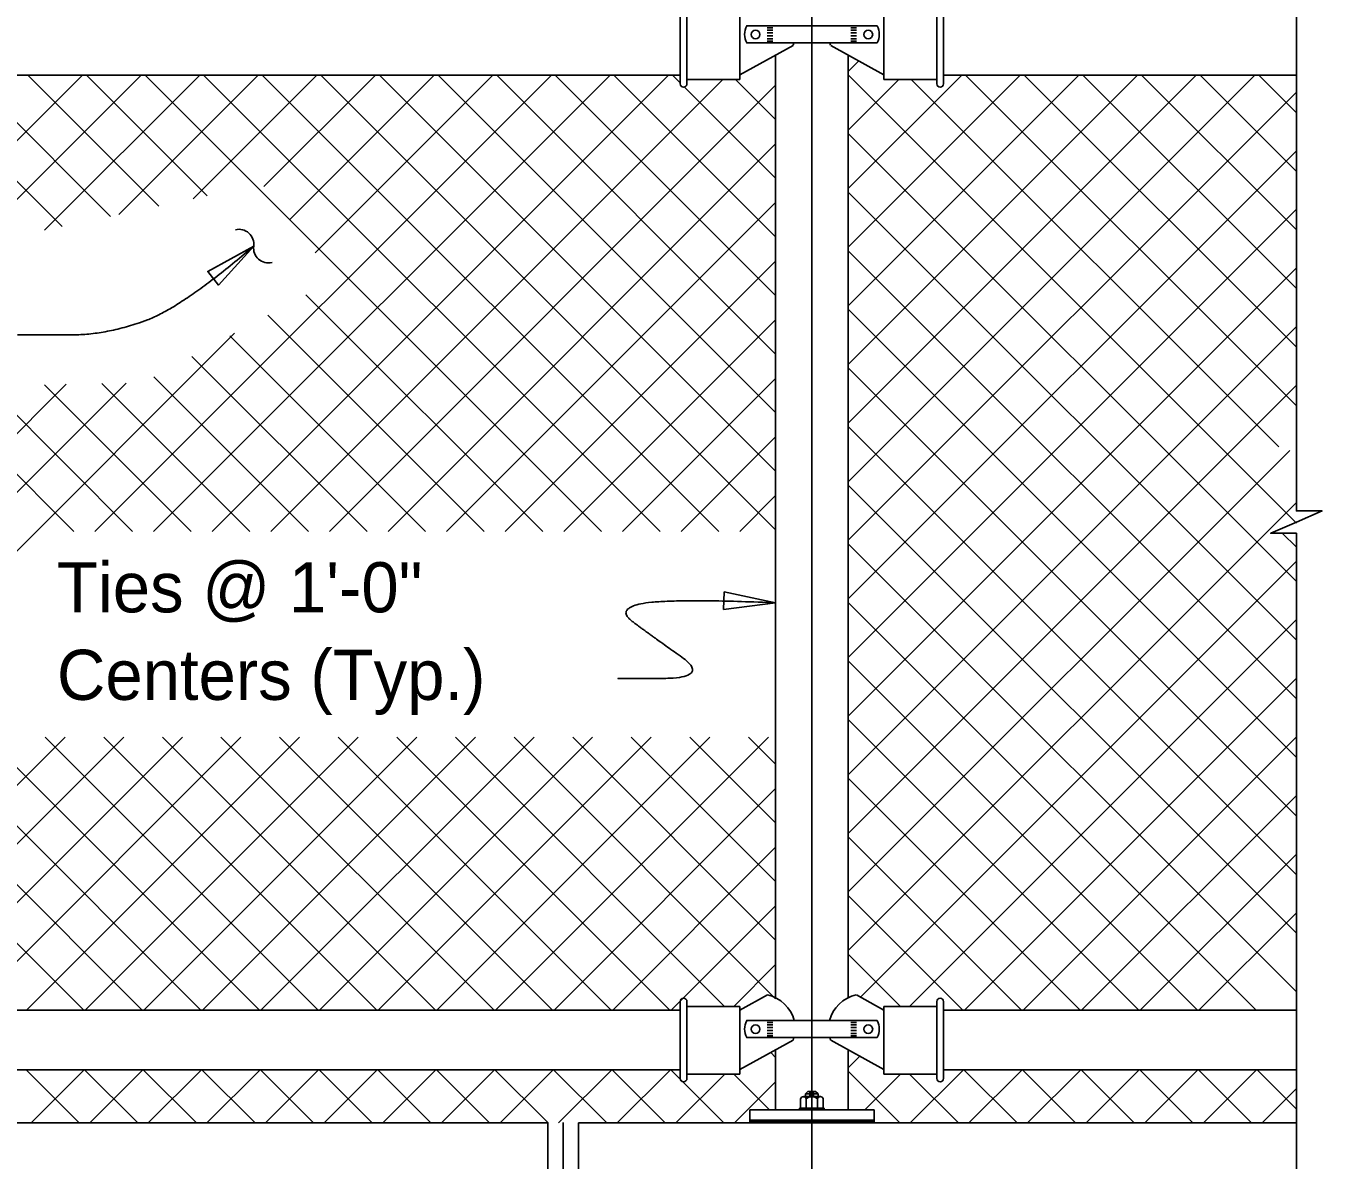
# Model space of a CAD drawing. Extents: x 110341.7 to 110413.5, y 110387.3 to 110417.8.
# Drawn here: x 110362.42 to 110367.63, y 110405.94 to 110410.5 of the extents above; entities that cross this region are included whole.
import ezdxf

# ---------------------------------------------------------------- set-up
doc = ezdxf.new("R2010")
doc.units = 0
for name, color, linetype in [('AdhocPoint_dp', 7, 'Continuous'), ('Border', 7, 'Continuous'), ('CL_Major', 7, 'Continuous'), ('Patterning', 7, 'Continuous'), ('PlotBorder_dp', 7, 'Continuous')]:
    doc.layers.add(name, color=color, linetype=linetype)

msp = doc.modelspace()

# ---------------------------------------------------------------- linework, layer by layer
at = {"layer": 'AdhocPoint_dp'}
for p, q in [((110365.0484, 110410.5816), (110365.0484, 110410.272)), ((110365.0753, 110410.5816), (110365.0753, 110410.272)), ((110365.2882, 110410.5621), (110365.2882, 110410.2898)), ((110365.8673, 110410.5621), (110365.8673, 110410.2898)), ((110366.0803, 110410.5816), (110366.0803, 110410.272)), ((110366.1071, 110410.5816), (110366.1071, 110410.272)), ((110365.8402, 110410.5047), (110365.3154, 110410.5047)), ((110365.3978, 110410.4969), (110365.4212, 110410.4969)), ((110365.3978, 110410.4873), (110365.4212, 110410.4873)), ((110365.3978, 110410.4765), (110365.4212, 110410.4765)), ((110365.3978, 110410.4647), (110365.4212, 110410.4647)), ((110365.7578, 110410.4969), (110365.7343, 110410.4969)), ((110365.7578, 110410.4873), (110365.7343, 110410.4873)), ((110365.7578, 110410.4765), (110365.7343, 110410.4765)), ((110365.7578, 110410.4647), (110365.7343, 110410.4647)), ((110365.2882, 110410.308), (110365.5022, 110410.4265)), ((110365.8402, 110410.4369), (110365.3154, 110410.4369)), ((110365.3978, 110410.453), (110365.4212, 110410.453)), ((110365.3978, 110410.4432), (110365.4212, 110410.4432)), ((110365.8673, 110410.308), (110365.6534, 110410.4265)), ((110365.7578, 110410.453), (110365.7343, 110410.453)), ((110365.7578, 110410.4432), (110365.7343, 110410.4432)), ((110365.432, 110406.5968), (110365.432, 110410.3876)), ((110365.7237, 110406.5968), (110365.7237, 110410.3876)), ((110365.0484, 110410.307), (110361.1164, 110410.307)), ((110367.5259, 110410.307), (110366.1071, 110410.307)), ((110365.0753, 110410.2898), (110365.2882, 110410.2898)), ((110366.0803, 110410.2898), (110365.8673, 110410.2898)), ((110365.2882, 110406.5473), (110365.3991, 110406.6087)), ((110365.8673, 110406.5473), (110365.7565, 110406.6087)), ((110365.0484, 110406.5466), (110361.1164, 110406.5466)), ((110365.0484, 110406.5816), (110365.0484, 110406.2719)), ((110365.0753, 110406.5816), (110365.0753, 110406.2719)), ((110365.2882, 110406.5621), (110365.0753, 110406.5621)), ((110365.2882, 110406.5621), (110365.2882, 110406.2898)), ((110365.8673, 110406.5621), (110365.8673, 110406.2898)), ((110365.8673, 110406.5621), (110366.0803, 110406.5621)), ((110366.0803, 110406.5816), (110366.0803, 110406.2719)), ((110366.1071, 110406.5816), (110366.1071, 110406.2719)), ((110367.5259, 110406.5466), (110366.1071, 110406.5466)), ((110365.8402, 110406.5047), (110365.3154, 110406.5047)), ((110365.3978, 110406.4969), (110365.4212, 110406.4969)), ((110365.7578, 110406.4969), (110365.7343, 110406.4969)), ((110365.3978, 110406.4873), (110365.4212, 110406.4873)), ((110365.3978, 110406.4765), (110365.4212, 110406.4765)), ((110365.3978, 110406.4647), (110365.4212, 110406.4647)), ((110365.3978, 110406.4529), (110365.4212, 110406.4529)), ((110365.3978, 110406.4431), (110365.4212, 110406.4431)), ((110365.7578, 110406.4873), (110365.7343, 110406.4873)), ((110365.7578, 110406.4765), (110365.7343, 110406.4765)), ((110365.7578, 110406.4647), (110365.7343, 110406.4647)), ((110365.7578, 110406.4529), (110365.7343, 110406.4529)), ((110365.7578, 110406.4431), (110365.7343, 110406.4431)), ((110365.2882, 110406.3079), (110365.5022, 110406.4265)), ((110365.8402, 110406.4369), (110365.3154, 110406.4369)), ((110365.8673, 110406.3079), (110365.6534, 110406.4265)), ((110365.432, 110406.1455), (110365.432, 110406.3876)), ((110365.7237, 110406.1455), (110365.7237, 110406.3875)), ((110365.0484, 110406.307), (110361.1164, 110406.307)), ((110365.0753, 110406.2898), (110365.2882, 110406.2898)), ((110366.0803, 110406.2898), (110365.8673, 110406.2898)), ((110367.5259, 110406.307), (110366.1071, 110406.307)), ((110365.5324, 110406.1903), (110365.5324, 110406.1526)), ((110365.6119, 110406.199), (110365.5437, 110406.199)), ((110365.5617, 110406.2199), (110365.552, 110406.2102)), ((110365.552, 110406.2102), (110365.552, 110406.199)), ((110365.552, 110406.2102), (110365.6035, 110406.2102)), ((110365.5551, 110406.1905), (110365.5551, 110406.1526)), ((110365.5617, 110406.2199), (110365.5922, 110406.2199)), ((110365.5922, 110406.2199), (110365.6035, 110406.2102)), ((110365.6005, 110406.1905), (110365.6005, 110406.1526)), ((110365.6035, 110406.2102), (110365.6035, 110406.199)), ((110365.6232, 110406.1903), (110365.6232, 110406.1526)), ((110365.5281, 110406.1526), (110365.5281, 110406.1455)), ((110365.5281, 110406.1526), (110365.6276, 110406.1526)), ((110365.6232, 110406.1526), (110365.5324, 110406.1526)), ((110365.6276, 110406.1526), (110365.6276, 110406.1455)), ((110365.458, 110406.1039), (110365.6976, 110406.1039))]:
    msp.add_line(p, q, dxfattribs=at)
msp.add_lwpolyline([(110365.3278, 110406.1455), (110365.8278, 110406.1455), (110365.8278, 110406.1039), (110365.3278, 110406.1039)], close=True, dxfattribs=at)
for centre, radius, start, end in [((110365.062, 110410.2717), 0.0134, 180, 0), ((110366.0936, 110410.2717), 0.0134, 180, 0), ((110365.062, 110406.5815), 0.0134, 0, 180), ((110366.0936, 110406.5815), 0.0134, 0, 180), ((110365.062, 110406.2717), 0.0134, 180, 0), ((110366.0936, 110406.2717), 0.0134, 180, 0), ((110365.5438, 110406.1871), 0.0118, 16.5986, 164.7005), ((110365.5778, 110406.1642), 0.0347, 49.2015, 130.7985), ((110365.6118, 110406.1872), 0.0118, 15.1506, 163.5042)]:
    msp.add_arc(centre, radius, start, end, dxfattribs=at)
for centre, major_axis, start_param, end_param in [((110365.3846, 110410.4707), (-0.0776, 0), 5.810211, 6.75616), ((110365.771, 110410.4707), (0.0776, 0), 5.810211, 6.75616), ((110365.3646, 110410.4727), (0.146, 0), 5.947976, 6.024627), ((110365.791, 110410.4727), (-0.146, 0), 0.258558, 0.335209), ((110365.3646, 110406.4727), (0.146, 0), 0.231126, 1.331255), ((110365.791, 110406.4727), (-0.146, 0), 4.95193, 6.05206), ((110365.3846, 110406.4707), (-0.0776, 0), 5.810211, 6.75616), ((110365.771, 110406.4707), (0.0776, 0), 5.810211, 6.75616), ((110365.3646, 110406.4727), (0.146, 0), 5.947976, 6.024627), ((110365.791, 110406.4727), (-0.146, 0), 0.258558, 0.335209)]:
    msp.add_ellipse(centre, major_axis=major_axis, ratio=0.957868, start_param=start_param, end_param=end_param, dxfattribs=at)
for centre, major_axis in [((110365.3512, 110410.4703), (0.0178, 0)), ((110365.8044, 110410.4703), (-0.0178, 0)), ((110365.3512, 110406.4703), (0.0178, 0)), ((110365.8044, 110406.4703), (-0.0178, 0))]:
    msp.add_ellipse(centre, major_axis=major_axis, ratio=0.957868, dxfattribs=at)
at = {"layer": 'Border'}
msp.add_line((110365.5778, 110406.1533), (110365.5778, 110406.1526), dxfattribs=at)
for points in [[(110367.5259, 110413.4227), (110367.5259, 110410.8892), (110367.6293, 110410.8892), (110367.5259, 110410.8442), (110367.4226, 110410.7992), (110367.5259, 110410.7992), (110367.5259, 110410.307)], [(110367.5259, 110410.307), (110367.5259, 110408.5545), (110367.6293, 110408.5545), (110367.5259, 110408.5095), (110367.4226, 110408.4645), (110367.5259, 110408.4645), (110367.5259, 110406.2602)], [(110367.5259, 110406.5102), (110367.5259, 110404.6594), (110367.6293, 110404.6594), (110367.5259, 110404.6144), (110367.4226, 110404.5694), (110367.5259, 110404.5694), (110367.5259, 110403.0269)]]:
    msp.add_lwpolyline(points, dxfattribs=at)
for points in [[(110363.3338, 110409.6187), (110363.1483, 110409.5178), (110363.1919, 110409.4623)], [(110365.432, 110408.1851), (110365.2253, 110408.2289), (110365.2225, 110408.1584)]]:
    msp.add_lwpolyline(points, close=True, dxfattribs=at)
for centre, start, end in [((110363.2743, 110409.6272), 352.3426, 104.0698), ((110363.3924, 110409.6113), 172.3426, 284.0698)]:
    msp.add_arc(centre, 0.0596, start, end, dxfattribs=at)
for points in [[(110362.3836, 110409.2623), (110362.4628, 110409.2623), (110362.7363, 110409.2623), (110363.0431, 110409.3702), (110363.3333, 110409.6192)], [(110364.8073, 110407.8805), (110364.7561, 110407.8805), (110365.1761, 110407.8805), (110364.9259, 110408.0576), (110364.7887, 110408.1603), (110364.9992, 110408.2028), (110365.432, 110408.1851)]]:
    msp.add_open_spline(points, degree=2, dxfattribs=at)
at = {"layer": 'CL_Major'}
for p, q in [((110365.5778, 110401.2111), (110365.5778, 110414.9771)), ((110364.5779, 110401.2111), (110364.5779, 110406.0949))]:
    msp.add_line(p, q, dxfattribs=at)
at = {"layer": 'Patterning'}
for p, q in [((110365.7237, 110410.3219), (110365.766, 110410.3642)), ((110361.9358, 110409.5981), (110362.6447, 110410.307)), ((110361.9534, 110410.307), (110362.5625, 110409.6979)), ((110362.1891, 110410.307), (110362.7571, 110409.739)), ((110362.1929, 110409.6196), (110362.8804, 110410.307)), ((110362.4248, 110410.307), (110362.9516, 110409.7802)), ((110362.492, 110409.6829), (110363.1161, 110410.307)), ((110362.6605, 110410.307), (110363.1461, 110409.8214)), ((110362.6948, 110408.4715), (110364.5303, 110410.307)), ((110362.791, 110409.7462), (110363.3518, 110410.307)), ((110362.8962, 110410.307), (110364.7317, 110408.4715)), ((110362.9305, 110408.4715), (110364.766, 110410.307)), ((110363.09, 110409.8095), (110363.5875, 110410.307)), ((110363.1319, 110410.307), (110364.9674, 110408.4715)), ((110363.1662, 110408.4715), (110365.0017, 110410.307)), ((110363.3676, 110410.307), (110365.2031, 110408.4715)), ((110363.3746, 110409.8584), (110363.8232, 110410.307)), ((110363.4774, 110409.7255), (110364.0589, 110410.307)), ((110363.5802, 110409.5926), (110364.2946, 110410.307)), ((110363.6033, 110410.307), (110365.432, 110408.4783)), ((110363.839, 110410.307), (110365.432, 110408.714)), ((110364.0747, 110410.307), (110365.432, 110408.9497)), ((110364.3104, 110410.307), (110365.432, 110409.1854)), ((110364.5461, 110410.307), (110365.432, 110409.4211)), ((110364.7818, 110410.307), (110365.432, 110409.6568)), ((110365.0175, 110410.307), (110365.0484, 110410.2761)), ((110365.7237, 110410.308), (110367.526, 110408.5057)), ((110365.7237, 110408.672), (110367.3587, 110410.307)), ((110365.7237, 110408.9077), (110367.123, 110410.307)), ((110365.7237, 110409.1434), (110366.8873, 110410.307)), ((110365.7237, 110409.6148), (110366.4159, 110410.307)), ((110365.7237, 110409.8505), (110366.1802, 110410.307)), ((110365.7237, 110409.3791), (110366.6516, 110410.307)), ((110366.196, 110410.307), (110367.526, 110408.9771)), ((110366.4317, 110410.307), (110367.526, 110409.2128)), ((110366.6674, 110410.307), (110367.526, 110409.4485)), ((110366.9031, 110410.307), (110367.526, 110409.6842)), ((110367.1388, 110410.307), (110367.526, 110409.9199)), ((110367.3745, 110410.307), (110367.526, 110410.1556)), ((110363.4019, 110408.4715), (110365.2203, 110410.2899)), ((110363.6376, 110408.4715), (110365.432, 110410.2659)), ((110365.0657, 110410.2588), (110365.432, 110409.8925)), ((110365.2704, 110410.2899), (110365.432, 110410.1282)), ((110365.7237, 110410.0862), (110365.9274, 110410.2899)), ((110365.9775, 110410.2899), (110367.4552, 110408.8121)), ((110365.7237, 110408.4363), (110367.526, 110410.2386)), ((110365.7237, 110410.0723), (110367.526, 110408.27)), ((110363.8733, 110408.4715), (110365.432, 110410.0302)), ((110365.7237, 110408.2006), (110367.526, 110410.0029)), ((110365.7237, 110409.8366), (110367.526, 110408.0343)), ((110364.109, 110408.4715), (110365.432, 110409.7945)), ((110365.7237, 110407.9649), (110367.526, 110409.7672)), ((110365.7237, 110409.6009), (110367.526, 110407.7986)), ((110364.3447, 110408.4715), (110365.432, 110409.5588)), ((110365.7237, 110407.7292), (110367.526, 110409.5315)), ((110363.5435, 110409.424), (110364.496, 110408.4715)), ((110365.7237, 110409.3652), (110367.526, 110407.5629)), ((110363.3905, 110409.3413), (110364.2603, 110408.4715)), ((110364.5804, 110408.4715), (110365.432, 110409.3231)), ((110360.5342, 110406.5466), (110363.2565, 110409.269)), ((110363.2375, 110409.2587), (110364.0246, 110408.4715)), ((110365.7237, 110407.4935), (110367.526, 110409.2958)), ((110363.0844, 110409.176), (110363.7889, 110408.4715)), ((110365.7237, 110409.1295), (110367.526, 110407.3272)), ((110360.0628, 110406.5466), (110362.5797, 110409.0635)), ((110360.2985, 110406.5466), (110362.8207, 110409.0688)), ((110362.0303, 110409.0515), (110362.6104, 110408.4715)), ((110362.261, 110409.0566), (110362.8461, 110408.4715)), ((110362.4917, 110409.0616), (110363.0818, 110408.4715)), ((110362.7223, 110409.0667), (110363.3175, 110408.4715)), ((110362.9314, 110409.0933), (110363.5532, 110408.4715)), ((110364.8161, 110408.4715), (110365.432, 110409.0874)), ((110365.7237, 110407.2578), (110367.526, 110409.0601)), ((110360.185, 110409.0112), (110362.6497, 110406.5466)), ((110360.4157, 110409.0163), (110362.8854, 110406.5466)), ((110360.6464, 110409.0213), (110363.1211, 110406.5466)), ((110360.877, 110409.0264), (110363.3568, 110406.5466)), ((110365.7237, 110408.8938), (110367.5259, 110407.0915)), ((110365.0518, 110408.4715), (110365.432, 110408.8517)), ((110365.7237, 110407.0221), (110367.4995, 110408.7979)), ((110365.7237, 110408.6581), (110367.5259, 110406.8558)), ((110365.2875, 110408.4715), (110365.432, 110408.616)), ((110365.7237, 110406.7864), (110367.526, 110408.5887)), ((110365.7237, 110408.4224), (110367.5259, 110406.6201)), ((110367.4694, 110408.4646), (110367.526, 110408.408)), ((110365.7727, 110406.5997), (110367.526, 110408.353)), ((110365.7237, 110408.1867), (110367.3637, 110406.5466)), ((110365.9708, 110406.5621), (110367.526, 110408.1172)), ((110365.7237, 110407.9509), (110367.128, 110406.5466)), ((110366.191, 110406.5466), (110367.526, 110407.8815)), ((110365.7237, 110407.7152), (110366.8923, 110406.5466)), ((110361.477, 110406.5466), (110362.5749, 110407.6446)), ((110361.7127, 110406.5466), (110362.8106, 110407.6446)), ((110361.9484, 110406.5466), (110363.0463, 110407.6446)), ((110362.1841, 110406.5466), (110363.282, 110407.6446)), ((110362.4198, 110406.5466), (110363.5177, 110407.6446)), ((110362.4945, 110407.6446), (110363.5925, 110406.5466)), ((110362.6555, 110406.5466), (110363.7534, 110407.6446)), ((110362.7302, 110407.6446), (110363.8282, 110406.5466)), ((110362.8912, 110406.5466), (110363.9891, 110407.6446)), ((110362.9659, 110407.6446), (110364.0639, 110406.5466)), ((110363.1269, 110406.5466), (110364.2248, 110407.6446)), ((110363.2016, 110407.6446), (110364.2996, 110406.5466)), ((110363.3626, 110406.5466), (110364.4605, 110407.6446)), ((110363.4373, 110407.6446), (110364.5353, 110406.5466)), ((110363.5983, 110406.5466), (110364.6962, 110407.6446)), ((110363.673, 110407.6446), (110364.771, 110406.5466)), ((110363.834, 110406.5466), (110364.932, 110407.6446)), ((110363.9087, 110407.6446), (110365.0067, 110406.5466)), ((110364.0697, 110406.5466), (110365.1677, 110407.6446)), ((110364.1444, 110407.6446), (110365.2269, 110406.5621)), ((110364.3054, 110406.5466), (110365.4034, 110407.6446)), ((110364.3801, 110407.6446), (110365.432, 110406.5927)), ((110364.6159, 110407.6446), (110365.432, 110406.8284)), ((110364.8516, 110407.6446), (110365.432, 110407.0641)), ((110365.0873, 110407.6446), (110365.432, 110407.2998)), ((110365.323, 110407.6446), (110365.432, 110407.5355)), ((110366.4267, 110406.5466), (110367.526, 110407.6458)), ((110364.5411, 110406.5466), (110365.432, 110407.4375)), ((110365.7237, 110407.4795), (110366.6566, 110406.5466)), ((110366.6624, 110406.5466), (110367.526, 110407.4101)), ((110365.7237, 110407.2438), (110366.4209, 110406.5466)), ((110364.7768, 110406.5466), (110365.432, 110407.2018)), ((110366.8981, 110406.5466), (110367.5259, 110407.1744)), ((110365.0125, 110406.5466), (110365.432, 110406.9661)), ((110365.7237, 110407.0081), (110366.1852, 110406.5466)), ((110367.1338, 110406.5466), (110367.5259, 110406.9387)), ((110365.7237, 110406.7724), (110365.9341, 110406.5621)), ((110365.2637, 110406.5621), (110365.432, 110406.7304)), ((110365.4123, 110406.3767), (110365.432, 110406.357)), ((110365.7237, 110406.3149), (110365.7704, 110406.3617)), ((110362.4178, 110406.307), (110362.6314, 110406.0935)), ((110362.4381, 110406.0935), (110362.6516, 110406.307)), ((110362.6535, 110406.307), (110362.8671, 110406.0935)), ((110362.6738, 110406.0935), (110362.8873, 110406.307)), ((110362.8892, 110406.307), (110363.1028, 110406.0935)), ((110362.9095, 110406.0935), (110363.123, 110406.307)), ((110363.125, 110406.307), (110363.3385, 110406.0935)), ((110363.1452, 110406.0935), (110363.3587, 110406.307)), ((110363.3607, 110406.307), (110363.5742, 110406.0935)), ((110363.3809, 110406.0935), (110363.5944, 110406.307)), ((110363.5964, 110406.307), (110363.8099, 110406.0935)), ((110363.6166, 110406.0935), (110363.8301, 110406.307)), ((110363.8321, 110406.307), (110364.0456, 110406.0935)), ((110363.8523, 110406.0935), (110364.0658, 110406.307)), ((110364.0678, 110406.307), (110364.2813, 110406.0935)), ((110364.088, 110406.0935), (110364.3015, 110406.307)), ((110364.3035, 110406.307), (110364.517, 110406.0935)), ((110364.3237, 110406.0935), (110364.5372, 110406.307)), ((110364.5392, 110406.307), (110364.7527, 110406.0934)), ((110364.5594, 110406.0935), (110364.7729, 110406.307)), ((110364.7749, 110406.307), (110364.9884, 110406.0934)), ((110364.7951, 110406.0934), (110365.0086, 110406.307)), ((110365.0106, 110406.307), (110365.2241, 110406.0934)), ((110365.0308, 110406.0934), (110365.2271, 110406.2898)), ((110365.2635, 110406.2898), (110365.4078, 110406.1455)), ((110365.7237, 110406.301), (110365.9313, 110406.0934)), ((110365.79, 110406.1455), (110365.9342, 110406.2898)), ((110365.9706, 110406.2898), (110366.167, 110406.0934)), ((110365.9736, 110406.0934), (110366.1871, 110406.307)), ((110366.1891, 110406.307), (110366.4027, 110406.0934)), ((110366.2093, 110406.0934), (110366.4229, 110406.307)), ((110366.4248, 110406.307), (110366.6384, 110406.0934)), ((110366.445, 110406.0934), (110366.6586, 110406.307)), ((110366.6605, 110406.307), (110366.8741, 110406.0934)), ((110366.6807, 110406.0934), (110366.8943, 110406.307)), ((110366.8962, 110406.307), (110367.1098, 110406.0934)), ((110366.9164, 110406.0934), (110367.13, 110406.307)), ((110367.1319, 110406.307), (110367.3455, 110406.0934)), ((110367.1521, 110406.0934), (110367.3657, 110406.307)), ((110367.3676, 110406.307), (110367.5259, 110406.1487)), ((110365.2665, 110406.0934), (110365.432, 110406.259)), ((110365.5666, 110406.215), (110365.5874, 110406.215)), ((110365.5666, 110406.2053), (110365.5874, 110406.2053)), ((110367.3878, 110406.0934), (110367.5259, 110406.2316)), ((110365.3278, 110406.1004), (110365.8278, 110406.1004)), ((110365.3278, 110406.0969), (110365.8278, 110406.0969))]:
    msp.add_line(p, q, dxfattribs=at)
msp.add_lwpolyline([(110365.3278, 110406.1039), (110365.8278, 110406.1039), (110365.8278, 110406.0935), (110365.3278, 110406.0935)], close=True, dxfattribs=at)
at = {"layer": 'PlotBorder_dp'}
for p, q in [((110357.2147, 110406.0935), (110364.5166, 110406.0935)), ((110364.5166, 110406.0935), (110364.5166, 110401.9888)), ((110364.6391, 110406.0935), (110364.6391, 110403.1769)), ((110367.5259, 110406.0934), (110364.6391, 110406.0934))]:
    msp.add_line(p, q, dxfattribs=at)

# ---------------------------------------------------------------- texts
at = {"layer": 'Border'}
for s, p in [('Ties @ 1\'-0" ', (110362.5422, 110408.1465)), ('Centers (Typ.)', (110362.5422, 110407.7945))]:
    msp.add_text(s, height=0.2016, dxfattribs=at).set_placement(p)

doc.saveas('drawing.dxf')
